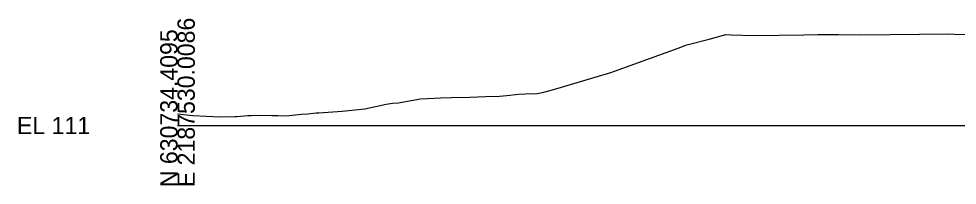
# Model space of a CAD drawing. Extents: x -26 to 2903, y -10 to 63.
# Drawn here: x 2574.3 to 2726.2, y -9.7 to 17.3 of the extents above; entities that cross this region are included whole.
import ezdxf

# ---------------------------------------------------------------- set-up
doc = ezdxf.new("R2010")
doc.units = 0
for name, color, linetype in [('Default', 7, 'Continuous'), ('Exist Cross Section Cell', 7, 'Continuous'), ('Exist XS Ground Line', 7, 'Continuous')]:
    doc.layers.add(name, color=color, linetype=linetype)

msp = doc.modelspace()

# ---------------------------------------------------------------- linework, layer by layer
at = {"layer": 'Exist Cross Section Cell'}
msp.add_line((2600, 0), (2750, 0), dxfattribs=at)
at = {"layer": 'Exist XS Ground Line'}
for p, q in [((2682.64, 13.12), (2686.04, 14)), ((2686.04, 14), (2688.73, 14.74)), ((2688.73, 14.74), (2689.59, 14.73)), ((2689.59, 14.73), (2693.33, 14.6)), ((2693.33, 14.6), (2701.39, 14.71)), ((2701.39, 14.71), (2703.64, 14.76)), ((2703.64, 14.76), (2706.99, 14.74)), ((2706.99, 14.74), (2710.59, 14.7)), ((2710.59, 14.7), (2724.84, 14.85)), ((2724.84, 14.85), (2725.78, 14.84)), ((2725.78, 14.84), (2729.46, 14.69)), ((2670.12, 8.62), (2681.02, 12.54)), ((2681.02, 12.54), (2682.29, 13.05)), ((2682.29, 13.05), (2682.64, 13.12)), ((2660.71, 5.78), (2668.16, 8.02)), ((2668.16, 8.02), (2670.12, 8.62)), ((2642.57, 4.49), (2644.36, 4.57)), ((2644.36, 4.57), (2647.32, 4.58)), ((2647.32, 4.58), (2649.91, 4.72)), ((2649.91, 4.72), (2652.14, 4.76)), ((2652.14, 4.76), (2653.32, 4.87)), ((2653.32, 4.87), (2655.17, 5.09)), ((2655.17, 5.09), (2657.37, 5.21)), ((2657.37, 5.21), (2657.96, 5.14)), ((2657.96, 5.14), (2659.31, 5.4)), ((2659.31, 5.4), (2660.71, 5.78)), ((2630.33, 2.69), (2633.79, 3.44)), ((2633.79, 3.44), (2634.8, 3.64)), ((2634.8, 3.64), (2635.79, 3.68)), ((2635.79, 3.68), (2639.01, 4.25)), ((2639.01, 4.25), (2639.34, 4.33)), ((2639.34, 4.33), (2641.6, 4.42)), ((2641.6, 4.42), (2642.57, 4.49)), ((2600, 1.92), (2602.48, 1.6)), ((2602.48, 1.6), (2604.7, 1.5)), ((2609.62, 1.47), (2611.38, 1.63)), ((2611.38, 1.63), (2611.92, 1.62)), ((2611.92, 1.62), (2613.36, 1.68)), ((2613.36, 1.68), (2615.25, 1.62)), ((2615.25, 1.62), (2616.23, 1.6)), ((2616.23, 1.6), (2617.59, 1.56)), ((2617.59, 1.56), (2620.06, 1.85)), ((2620.06, 1.85), (2621.09, 1.88)), ((2621.09, 1.88), (2622.44, 2.06)), ((2622.44, 2.06), (2622.89, 2.08)), ((2622.89, 2.08), (2626.63, 2.31)), ((2626.63, 2.31), (2630.33, 2.69)), ((2604.7, 1.5), (2606.79, 1.39)), ((2606.79, 1.39), (2609.29, 1.45)), ((2609.29, 1.45), (2609.62, 1.47))]:
    msp.add_line(p, q, dxfattribs=at)

# ---------------------------------------------------------------- texts
at = {"layer": 'Default'}
msp.add_text('-', height=0.0001, dxfattribs=at).set_placement((2600, 0))
at = {"layer": 'Exist Cross Section Cell'}
for s, p in [('E 2187530.0086', (2602.8, -10)), ('N 630734.4095', (2600, -10))]:
    msp.add_text(s, height=2.8, rotation=90, dxfattribs=at).set_placement(p)
msp.add_text('EL 111', height=2.8, dxfattribs=at).set_placement((2574, -1.4))

doc.saveas('drawing.dxf')
